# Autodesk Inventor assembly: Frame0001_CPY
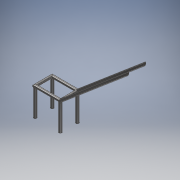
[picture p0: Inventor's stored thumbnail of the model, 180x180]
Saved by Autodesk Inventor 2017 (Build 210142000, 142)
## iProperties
Created: 2017-11
Part Number: Frame0001_CPY
Document SubType Name: Assembly
Designer: iusti
Mass: 7.38505e+06 g
Surface Area: 1.18279e+06 cm^2
Volume: 940770 cm^3
Density: 7.85 g/cm^3
Author: iusti
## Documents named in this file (21)
- C:\Users\iusti\Desktop\pasarela\Schelet pasarela\Frame\Frame0001_CPY.iam
- C:\Users\iusti\Desktop\pasarela\Schelet pasarela\Frame\DIN 150 x 150 x 16 00000100_CPY.ipt
- DIN 150 x 150 x 16 00000100.ipt
- C:\Users\iusti\Desktop\pasarela\Schelet pasarela\Frame\DIN 150 x 150 x 16 00000101_CPY.ipt
- DIN 150 x 150 x 16 00000101.ipt
- C:\Users\iusti\Desktop\pasarela\Schelet pasarela\Frame\DIN 150 x 150 x 16 00000102_CPY.ipt
- DIN 150 x 150 x 16 00000102.ipt
- C:\Users\iusti\Desktop\pasarela\Schelet pasarela\Frame\DIN 150 x 150 x 16 00000103_CPY.ipt
- DIN 150 x 150 x 16 00000103.ipt
- C:\Users\iusti\Desktop\pasarela\Schelet pasarela\Frame\DIN 150 x 150 x 16 00000104_CPY.ipt
- DIN 150 x 150 x 16 00000104.ipt
- C:\Users\iusti\Desktop\pasarela\Schelet pasarela\Frame\DIN 150 x 150 x 16 00000105_CPY.ipt
- DIN 150 x 150 x 16 00000105.ipt
- C:\Users\iusti\Desktop\pasarela\Schelet pasarela\Frame\DIN 150 x 150 x 16 00000106_CPY.ipt
- DIN 150 x 150 x 16 00000106.ipt
- C:\Users\iusti\Desktop\pasarela\Schelet pasarela\Frame\DIN 150 x 150 x 16 00000107_CPY.ipt
- DIN 150 x 150 x 16 00000107.ipt
- C:\Users\iusti\Desktop\pasarela\Schelet pasarela\Frame\DIN 150 x 150 x 16 00000108_CPY.ipt
- DIN 150 x 150 x 16 00000108.ipt
- C:\Users\iusti\Desktop\pasarela\Schelet pasarela\Frame\DIN 150 x 150 x 16 00000109_CPY.ipt
- DIN 150 x 150 x 16 00000109.ipt
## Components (10 placed, 10 different names)
1. DIN 150 x 150 x 16 00000100:1
2. DIN 150 x 150 x 16 00000101:1
3. DIN 150 x 150 x 16 00000102:1
4. DIN 150 x 150 x 16 00000103:1
5. DIN 150 x 150 x 16 00000104:1
6. DIN 150 x 150 x 16 00000105:1
7. DIN 150 x 150 x 16 00000106:1
8. DIN 150 x 150 x 16 00000107:1
9. DIN 150 x 150 x 16 00000108:1
10. DIN 150 x 150 x 16 00000109:1
